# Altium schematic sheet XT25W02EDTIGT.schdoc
size 127 x 101 mm
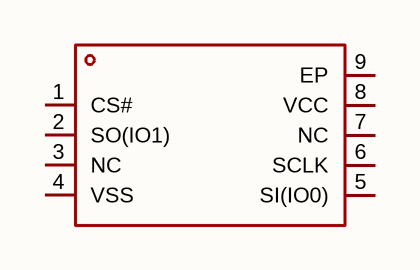
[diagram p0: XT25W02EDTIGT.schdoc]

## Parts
U?  xt25w02edtigt  [DFN-8_L3.0-W2.0-P0.50-BL-EP_XT25XXX]  (value not drawn)

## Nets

Not connected (* = marked no-connect by the designer): U? 1(CS#) 2(SO(IO1)) 3(NC) 4(VSS) 5(SI(IO0)) 6(SCLK) 7(NC) 8(VCC) 9(EP)

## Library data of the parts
U? = xt25w02edtigt: 接口类型:SPI;存储容量:2Mbit;时钟频率(fc):60MHz;; Manufacturer: XTX(芯天下); AddInBom: yes; ModelId: 12a239e5c7384371915ecb51201bf581; ModelName: USON-8_L3.0-W2.0-H0.6-P0.50; ModelTransform: 118.8974,78.74,0,90,0,0,0,0,0; Interface: SPI; Memory Size: 2Mbit; Clock Frequency: 60MHz; Voltage - Supply: 1.65V~3.6V; Standby Supply Current: 13uA; Program / Erase Cycles: 100000次; Page Programming Time (Tpp): 2.5ms; Block Erase Time(tBE): 800ms@(64KB); Data Retention - TDR (Year): 20年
